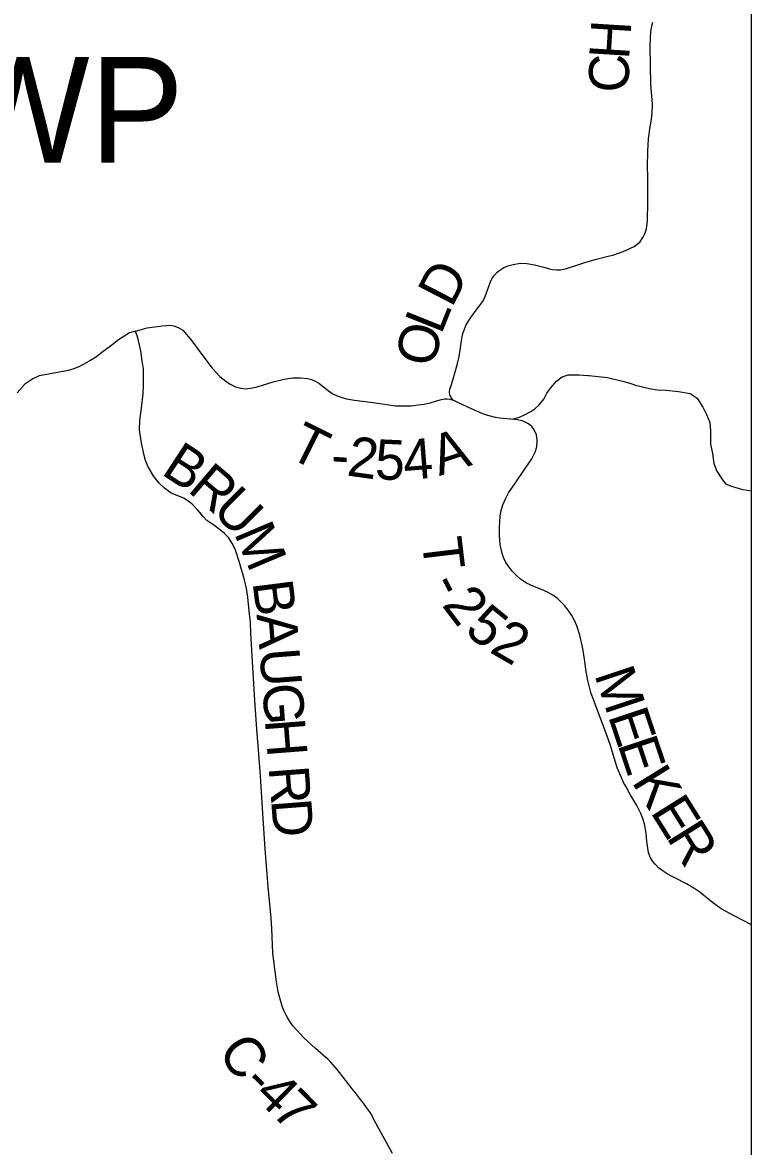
# Model space of a CAD drawing. Extents: x -10.5 to 40.6, y -3.2 to 22.
# Drawn here: x -4.779 to -3.744, y 17.441 to 19.035 of the extents above; entities that cross this region are included whole.
import ezdxf

# ---------------------------------------------------------------- set-up
doc = ezdxf.new("R2010")
doc.units = 0
for name, color, linetype in [('GM_X_County_Road', 7, 'Continuous'), ('GM_X_County_Road_Text', 7, 'Continuous'), ('GM_X_Township_Road', 7, 'Continuous'), ('GM_X_Township_Road_Text', 7, 'Continuous'), ('GM_X_Township_Text', 7, 'Continuous')]:
    doc.layers.add(name, color=color, linetype=linetype)

msp = doc.modelspace()

# ---------------------------------------------------------------- linework, layer by layer
at = {"layer": 'GM_X_County_Road'}
msp.add_lwpolyline([(-4.2536, 17.4307), (-4.2776, 17.4736), (-4.2852, 17.4883), (-4.2908, 17.4959), (-4.295, 17.502), (-4.3005, 17.5093), (-4.3046, 17.5149), (-4.3108, 17.5225), (-4.3203, 17.5347), (-4.3324, 17.5498), (-4.3414, 17.5603), (-4.345, 17.5641), (-4.3632, 17.5797), (-4.38, 17.5954), (-4.3891, 17.6052), (-4.3949, 17.6115), (-4.3984, 17.6166), (-4.4022, 17.6228), (-4.4044, 17.627), (-4.4077, 17.6337), (-4.4102, 17.6398), (-4.4132, 17.6494), (-4.4158, 17.6602), (-4.4182, 17.674), (-4.4204, 17.6888), (-4.4236, 17.7147), (-4.425, 17.7499), (-4.4257, 17.7644), (-4.4299, 17.8089), (-4.4343, 17.8628), (-4.4377, 17.9129), (-4.441, 17.9665), (-4.4445, 18.0096), (-4.4456, 18.026), (-4.4489, 18.0732), (-4.4519, 18.1205), (-4.4548, 18.1689), (-4.4554, 18.1846), (-4.4564, 18.1957), (-4.459, 18.2197), (-4.461, 18.2324), (-4.4639, 18.2445), (-4.471, 18.2693), (-4.4767, 18.2867), (-4.4808, 18.2957), (-4.4866, 18.3045), (-4.4919, 18.3101), (-4.4975, 18.3147), (-4.5074, 18.322), (-4.5171, 18.3289), (-4.5222, 18.3342), (-4.53, 18.3435), (-4.5386, 18.3525), (-4.5436, 18.3563), (-4.5497, 18.3602), (-4.5676, 18.3677), (-4.5774, 18.3744), (-4.5848, 18.3816), (-4.5923, 18.3911), (-4.6003, 18.4049), (-4.6041, 18.4138), (-4.6066, 18.4228), (-4.6103, 18.4414), (-4.6126, 18.4572), (-4.6122, 18.4706), (-4.6098, 18.4883), (-4.6074, 18.5091), (-4.6069, 18.52), (-4.6068, 18.5307), (-4.6072, 18.5438), (-4.6087, 18.5554), (-4.6108, 18.5693), (-4.6149, 18.5878), (-4.6183, 18.5974), (-4.6269, 18.5948), (-4.6426, 18.5852), (-4.6539, 18.576), (-4.6659, 18.567), (-4.6749, 18.5601), (-4.6831, 18.555), (-4.6985, 18.5466), (-4.7073, 18.5434), (-4.7159, 18.5408), (-4.7551, 18.5337), (-4.7641, 18.5299), (-4.7753, 18.5219), (-4.7862, 18.5097)], dxfattribs=at)
at = {"layer": 'GM_X_Township_Road'}
for points in [[(-4.1677, 18.4992), (-4.1712, 18.5036), (-4.1726, 18.5068), (-4.1729, 18.5107), (-4.1724, 18.5148), (-4.1707, 18.5201), (-4.1686, 18.5263), (-4.1621, 18.5495), (-4.1594, 18.5616), (-4.1579, 18.5705), (-4.1558, 18.5835), (-4.1549, 18.5894), (-4.1538, 18.5941), (-4.1523, 18.5987), (-4.1495, 18.6053), (-4.1456, 18.6124), (-4.1425, 18.6167), (-4.1349, 18.627), (-4.1283, 18.6354), (-4.125, 18.6402), (-4.1221, 18.6467), (-4.1184, 18.657), (-4.1141, 18.6685), (-4.1119, 18.673), (-4.1092, 18.6767), (-4.1053, 18.6808), (-4.1003, 18.6848), (-4.096, 18.6876), (-4.0902, 18.6901), (-4.0826, 18.6921), (-4.0726, 18.6936), (-4.0632, 18.6934), (-4.0523, 18.6913), (-4.0392, 18.688), (-4.031, 18.6857), (-4.0268, 18.6849), (-4.0211, 18.6843), (-4.0153, 18.6844), (-4.0082, 18.6857), (-3.9924, 18.6911), (-3.981, 18.6949), (-3.9662, 18.6989), (-3.9516, 18.7026), (-3.94, 18.7056), (-3.9264, 18.7101), (-3.9111, 18.7175), (-3.903, 18.7237), (-3.8985, 18.73), (-3.8959, 18.7352), (-3.8935, 18.7425), (-3.8921, 18.7542), (-3.8914, 18.7799), (-3.8918, 18.8174), (-3.8919, 18.8305), (-3.8917, 18.8527), (-3.8905, 18.8703), (-3.8881, 18.8872), (-3.8867, 18.8954), (-3.8853, 18.9061), (-3.8851, 18.9196), (-3.8875, 18.9472), (-3.8881, 19.0012), (-3.8879, 19.0134), (-3.8872, 19.0217), (-3.886, 19.0306), (-3.8846, 19.0356)], [(-4.6183, 18.5974), (-4.6018, 18.6019), (-4.5806, 18.6051), (-4.5703, 18.606), (-4.5641, 18.6051), (-4.5577, 18.6026), (-4.5512, 18.5987), (-4.5384, 18.5835), (-4.5242, 18.5642), (-4.5094, 18.5449), (-4.4985, 18.5329), (-4.4903, 18.5262), (-4.4841, 18.5219), (-4.4764, 18.5181), (-4.4687, 18.5164), (-4.4627, 18.5157), (-4.455, 18.5164), (-4.4459, 18.5185), (-4.4231, 18.5255), (-4.4073, 18.5293), (-4.3954, 18.5309), (-4.3841, 18.5311), (-4.3744, 18.5302), (-4.3688, 18.5288), (-4.3635, 18.5266), (-4.3582, 18.5233), (-4.345, 18.5129), (-4.338, 18.5079), (-4.3271, 18.5035), (-4.3189, 18.5013), (-4.3076, 18.4993), (-4.281, 18.496), (-4.2495, 18.4916), (-4.2272, 18.4916), (-4.2172, 18.4926), (-4.2088, 18.4937), (-4.2002, 18.4956), (-4.1915, 18.4984), (-4.1844, 18.5004), (-4.1801, 18.5011), (-4.1764, 18.5013), (-4.1726, 18.5006), (-4.1677, 18.4992)], [(-4.086, 18.4726), (-4.0803, 18.4736), (-4.0737, 18.4754), (-4.0655, 18.479), (-4.0574, 18.4835), (-4.0519, 18.4872), (-4.0459, 18.4928), (-4.0391, 18.501), (-4.0348, 18.5095), (-4.029, 18.5171), (-4.0211, 18.5266), (-4.0129, 18.5327), (-4.0044, 18.5355), (-3.9891, 18.5355), (-3.9767, 18.5346), (-3.9753, 18.5344)], [(-3.9753, 18.5344), (-3.949, 18.5318), (-3.9255, 18.5258), (-3.9173, 18.5234), (-3.9091, 18.5206), (-3.8891, 18.5162), (-3.8785, 18.5139), (-3.8655, 18.5136), (-3.8479, 18.5117), (-3.8317, 18.5091), (-3.8217, 18.5024), (-3.8135, 18.4893), (-3.8084, 18.4789), (-3.8035, 18.4677), (-3.8026, 18.456), (-3.8026, 18.4371), (-3.8, 18.4236), (-3.7978, 18.4096), (-3.7937, 18.3989), (-3.7866, 18.3877), (-3.7814, 18.3805), (-3.7735, 18.3772), (-3.7569, 18.3727), (-3.7445, 18.3706)], [(-4.086, 18.4726), (-4.0968, 18.4732), (-4.1017, 18.4737), (-4.1075, 18.4749), (-4.1185, 18.4777), (-4.1255, 18.48), (-4.1408, 18.4866), (-4.1612, 18.496), (-4.1677, 18.4992)], [(-3.9812, 18.1321), (-3.9837, 18.1471), (-3.9878, 18.1659), (-3.9922, 18.1792), (-3.9955, 18.187), (-3.9993, 18.1938), (-4.0044, 18.2013), (-4.01, 18.2082), (-4.0145, 18.2128), (-4.0194, 18.2177), (-4.0262, 18.223), (-4.035, 18.2276), (-4.0422, 18.2306), (-4.0535, 18.2352), (-4.0587, 18.2372), (-4.0638, 18.24), (-4.0723, 18.2457), (-4.0775, 18.25), (-4.0839, 18.2568), (-4.0884, 18.2626), (-4.0928, 18.2693), (-4.0964, 18.276), (-4.0983, 18.2818), (-4.0996, 18.2886), (-4.1009, 18.2942), (-4.1021, 18.3082), (-4.102, 18.3176), (-4.1017, 18.3282), (-4.1005, 18.3389), (-4.0993, 18.3444), (-4.0971, 18.3508), (-4.0932, 18.3606), (-4.0891, 18.3679), (-4.0804, 18.3809), (-4.0655, 18.4024), (-4.0612, 18.4084), (-4.0562, 18.4164), (-4.0513, 18.4258), (-4.0492, 18.433), (-4.0484, 18.4424), (-4.0495, 18.4504), (-4.0529, 18.4572), (-4.0561, 18.462), (-4.0608, 18.4657), (-4.0685, 18.4696), (-4.0766, 18.4714), (-4.0805, 18.4721), (-4.086, 18.4726)], [(-3.7445, 17.7551), (-3.7689, 17.7677), (-3.7874, 17.7779), (-3.8, 17.7867), (-3.8179, 17.8016), (-3.8262, 17.8073), (-3.8366, 17.813), (-3.8525, 17.8212), (-3.8629, 17.8264), (-3.87, 17.8314), (-3.8763, 17.8361), (-3.8811, 17.8409), (-3.8843, 17.8451), (-3.8882, 17.851), (-3.8906, 17.8579), (-3.8931, 17.8732), (-3.8938, 17.8853), (-3.8965, 17.8985), (-3.8987, 17.906), (-3.9017, 17.9128), (-3.9077, 17.9251), (-3.9166, 17.94), (-3.9224, 17.9507), (-3.9262, 17.9572), (-3.9296, 17.9648), (-3.935, 17.9778), (-3.9401, 17.9952), (-3.9448, 18.0108), (-3.9491, 18.0226), (-3.9669, 18.0694), (-3.9723, 18.0848), (-3.9768, 18.1018), (-3.9793, 18.1175), (-3.9807, 18.1293), (-3.9812, 18.1321)]]:
    msp.add_lwpolyline(points, dxfattribs=at)
at = {"layer": 'GM_X_Township_Text'}
msp.add_lwpolyline([(-3.7445, 16.8499), (-3.7445, 20.9), (-6.1618, 20.9)], dxfattribs=at)

# ---------------------------------------------------------------- texts
at = {"layer": 'GM_X_County_Road_Text'}
for s, rotation, p in [('B', 326.8382, (-4.5835, 18.3953)), ('R', 319.6857, (-4.546, 18.3709)), ('U', 315.0515, (-4.5113, 18.3415)), ('M', 292.9632, (-4.4791, 18.311)), ('B', 277.2712, (-4.4524, 18.2411)), ('A', 274.5728, (-4.4466, 18.1955)), ('U', 274.4415, (-4.4426, 18.1457)), ('G', 274.4416, (-4.4387, 18.0958)), ('H', 274.4433, (-4.4349, 18.046)), ('R', 274.4421, (-4.4296, 17.9787)), ('D', 274.4416, (-4.426, 17.9321)), ('C', 305.1656, (-4.5029, 17.575)), ('-', 315.9062, (-4.4685, 17.528)), ('4', 315.4305, (-4.4519, 17.5119)), ('7', 314.5731, (-4.4271, 17.4875))]:
    msp.add_text(s, height=0.0568, rotation=rotation, dxfattribs=at).set_placement(p)
at = {"layer": 'GM_X_Township_Road_Text'}
for s, rotation, p in [('H', 86.4241, (-3.9182, 18.9818)), ('C', 89.9688, (-3.9182, 18.936)), ('D', 62.6383, (-4.1697, 18.6293)), ('L', 68.2225, (-4.1848, 18.5912)), ('O', 77.9185, (-4.1946, 18.5447)), ('T', 333.3104, (-4.404, 18.4197)), ('A', 18.2701, (-4.1874, 18.3918)), ('2', 352.154, (-4.3198, 18.3927)), ('5', 357.443, (-4.2794, 18.3874)), ('4', 4.6041, (-4.2367, 18.386)), ('-', 356.4423, (-4.342, 18.3941)), ('T', 276.8561, (-4.2126, 18.3018)), ('-', 297.3113, (-4.2011, 18.2385)), ('2', 307.2358, (-4.1847, 18.2087)), ('5', 320.9595, (-4.1532, 18.1702)), ('2', 330.1703, (-4.1178, 18.1426)), ('M', 288.3369, (-3.9678, 18.1104)), ('E', 288.332, (-3.9484, 18.0518)), ('E', 288.445, (-3.9349, 18.0114)), ('K', 301.9567, (-3.9154, 17.9581)), ('E', 302.0615, (-3.8889, 17.9155)), ('R', 302.0087, (-3.8663, 17.8795))]:
    msp.add_text(s, height=0.0568, rotation=rotation, dxfattribs=at).set_placement(p)
at = {"layer": 'GM_X_Township_Text'}
msp.add_text('TWP', height=0.15, rotation=0, dxfattribs=at).set_placement((-4.9953, 18.8363))

doc.saveas('drawing.dxf')
